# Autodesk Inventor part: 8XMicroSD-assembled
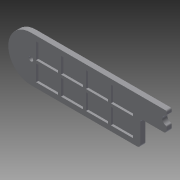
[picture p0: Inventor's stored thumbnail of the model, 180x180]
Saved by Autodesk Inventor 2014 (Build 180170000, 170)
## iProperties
Created: 2015-01
Part Number: 8XMicroSD-assembled
Material: Generic
Document SubType Name: Modeling
Designer: Drano
Density: 1 g/cm^3
Appearance: Default
Author: Drano
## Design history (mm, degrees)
derived "8XMicroSD.iam"
body "Solid1"
node "backplate.ipt:1" dims "d0" = 10
node "8XMicroSD.ipt:1" dims "d0" = 10
node "8XMicroSD.iam_Bodies" dims "d0" = 10
